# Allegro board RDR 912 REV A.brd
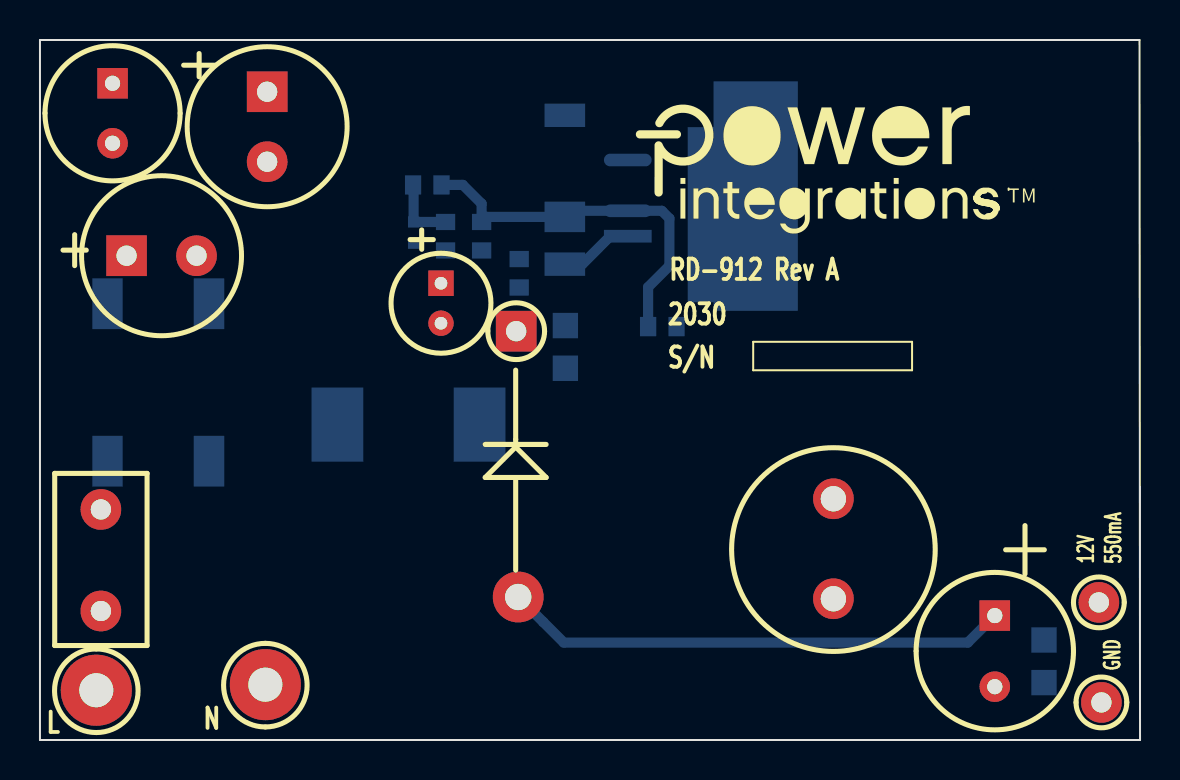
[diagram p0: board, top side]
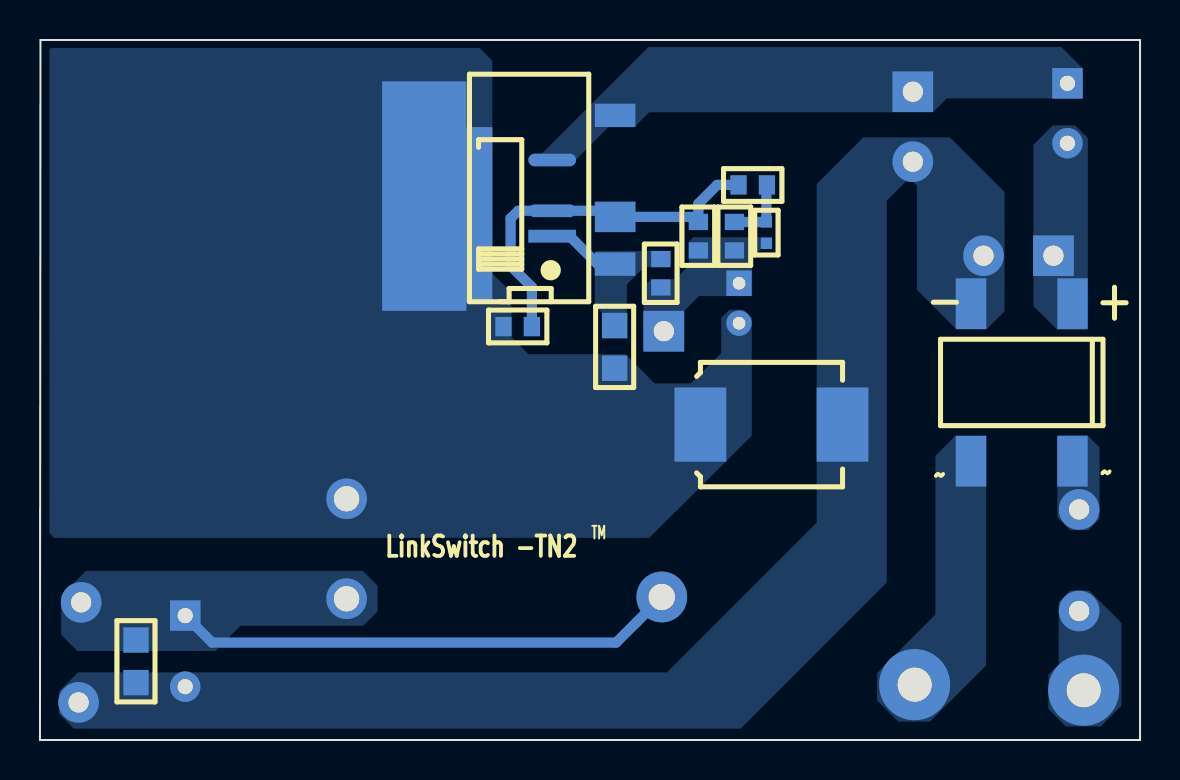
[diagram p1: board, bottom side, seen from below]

Outline 55.04 x 35.01 mm; copper layers: TOP, BOTTOM. Coordinates in mm from the lower left corner of the outline.
Outline path: 0,35.01 0,0 55.04,0 55.02,35.01 0,35.01

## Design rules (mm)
constraint set DEFAULT: min track width 0.508

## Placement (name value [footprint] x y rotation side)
C1  15  uF  [PI_POLCAPD8XH16XLLS3P5MM063H]  4.33 24.22 0 top
C2  15  uF  [PI_POLCAPD8XH16XLLS3P5MM063H]  11.37 32.42 270 top
C3  100 nF  [PISMC0805]  26.29 20.73 270 bottom
C4  10 uF  [PIPOLCAPCLYD5MMLS2MM025]  20.07 21.84 270 top
C5  220 uF  [PIPOLCAPCLYD320LS140030]  47.78 6.22 270 top
C6  1000 pF  [PISMC0603]  22.1 25.91 270 bottom
D1  DF06S-E3/45  [PISMDDFS]  3.38 21.77 180 bottom
D3  STTH3R06S  [PISMDO214AB12]  22 15.77 180 bottom
D4  1N4005GP-E3/54  [PIDV200X110X040DO41]  23.93 14.53 270 top
F1  1 A  [PI_RST_MICROFUSE]  3.05 11.53 270 top
L1  470 uH  [PI_CHOKE_RL5480-2_D2]  3.63 32.84 270 top
L2  680 uH  [PI_CHOKE_2P_D400LS200D05]  39.7 12.06 270 top
NOREF  -  []  55.02 35.01 270 top
NOREF#2  -  []  -150.78 61.85 0 top
NOREF#3  -  []  29.82 31.75 0 top
NOREF#4  -  []  -228.6 -137.16 0 top
NOREF#5  -  []  0 35.01 0 top
R1  2.49 k  [PISMR0603]  30.43 20.68 0 bottom
R2  12.1 k  [PISMR0603]  20.09 27.76 180 bottom
R3  27 k  [PISMR0603]  23.98 24.05 270 bottom
R4  20 k  [PISMR0805]  50.24 5 270 bottom
R5  6.81 k  [PISMR0603]  20.29 25.91 270 bottom
R6  0.0  [PISMR0402]  18.69 25.91 270 bottom
TP1  WHT  [PITPKEYSTONE125X125]  2.82 2.49 0 top
TP2  BLK  [PITPKEYSTONE125X125]  11.28 2.77 0 top
TP3  RED  [PITPKEYSTONE100X100]  52.98 6.88 270 top
TP4  BLK  [PITPKEYSTONE100X100]  53.11 1.88 270 top
U1  LNK3207D  [PISMSO8DNSHORT5678]  29.41 25.2 90 bottom
U2  LNK3207GN  [PIICSMD8CSHORT5678]  26.26 23.8 90 bottom

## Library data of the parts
C1 C2 = CAP POL: alternate symbols: (PI_POLCAPD8mmxlLS3p5mm063V)
C3 C6 = CAP NP
C4 = CAP POL
C5 = CAP POL: alternate symbols: (pipolcapclyd320ls140030430h)
D1 = DIODE BRIDGE_+-~~
D3 = DIODE
D4 = DIODE: alternate symbols: (pidv200x110x040do41A,pidax475x125040do41,pidv200x110x040do41wbead,pidax390x125040do41)
F1 = FUSE: alternate symbols: (pirstmicrofusehoz)
L1 = INDUCTOR_DOT2: alternate symbols: (pi_choke_RL5480-2H_d2)
L2 = INDUCTOR_DOT1: alternate symbols: (pi_choke_2p_d400ls200d05H)
R1-R5 = R
R6 = R: alternate symbols: (RC0402)
TP1-TP3 = TESTPOINT
TP4 = TESTPOINT: alternate symbols: (TP_TH_CR2_D1_1)
U1 U2 = LNK32XX_8C

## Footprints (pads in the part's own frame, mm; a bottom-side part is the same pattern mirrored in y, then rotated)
PI_CHOKE_2P_D400LS200D05
  round 2.032 hole 1.27: 1(0,0) 2(5,0)
PI_CHOKE_RL5480-2_D2
  rect 1.524x1.524 hole 0.762: 1(0,0)
  round 1.524 hole 0.762: 2(2.997,0)
PI_POLCAPD8XH16XLLS3P5MM063H
  rect 2.032x2.032 hole 1.016: 1(0,0)
  round 2.032 hole 1.016: 2(3.5,0)
PI_RST_MICROFUSE
  round 2.032 hole 1.016: 1(0,0) 2(5.08,0)
PIDV200X110X040DO41
  rect 2.032x2.032 hole 1.016: 1(-5.918,-0.102)
  round 2.54 hole 1.321: 2(7.376,0)
PIICSMD8CSHORT5678
  rect 1.168x2.032 smd: 1(0,0) 4(7.442,0) 5(7.442,8.636) 8(0,8.636)
  rect 1.524x2.032 smd: 2(2.362,0) 6(4.902,8.636) 7(2.362,8.636)
PIPOLCAPCLYD5MMLS2MM025
  rect 1.27x1.27 hole 0.635: 1(-1,0)
  round 1.27 hole 0.635: 2(1,0)
PIPOLCAPCLYD320LS140030
  rect 1.524x1.524 hole 0.762: 1(0,0)
  round 1.524 hole 0.762: 2(3.556,0)
PISMC0603
  rect 0.813x0.965 smd: 1(0,0) 2(1.422,0)
PISMC0805
  rect 1.27x1.27 smd: 1(0,0) 2(2.134,0)
PISMDDFS
  rect 1.524x2.54 smd: 1(0,0.051) 2(-5.08,0.051) 3(0,-7.823) 4(-5.08,-7.823)
PISMDO214AB12
  rect 2.591x3.708 smd: 1(0,0) 2(7.112,0)
PISMR0402
  rect 0.559x0.559 smd: 1(0,0) 2(1.067,0)
PISMR0603
  rect 0.813x0.965 smd: 1(0,0) 2(1.422,0)
PISMR0805
  rect 1.27x1.27 smd: 1(0,0) 2(2.134,0)
PISMSO8DNSHORT5678
  rect 0.635x2.388 smd: 1(0,0)
  oval 0.635x2.388 smd: 2(1.27,0) 4(3.81,0) 5(3.81,4.978) 6(2.54,4.978) 7(1.27,4.978) 8(0,4.978)
PITPKEYSTONE100X100
  round 2.032 hole 1.016: 1(0,0)
PITPKEYSTONE125X125
  round 3.556 hole 1.702: 1(0,0)

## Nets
SOURCE: U1.6 U1.7 U1.8 U2.6 U2.7 U2.8
N4183667: C2.1 L1.1 U1.4 U2.4
N4183681: C1.2 C2.2 C5.2 D1.2 D3.2 R4.2 TP4.1
N4183878: C3.2 C4.2 D3.1 L2.1 R1.2 U1.5(S) U2.5(S)
N4183892: C3.1 R3.1 U1.1 U2.1
N4184371: C6.1 R1.1 R2.1 U1.2 U2.2
N4185002: C5.1 D4.2 L2.2 R4.1 TP3.1
N4185015: C4.1 C6.2 D4.1 R3.2 R5.2 R6.2
N4189997: F1.2 TP1.1
N4190803: C1.1 D1.1 L1.2
N4191135: D1.3 F1.1
N4191491: D1.4 TP2.1
N4200643: R2.2 R5.1 R6.1

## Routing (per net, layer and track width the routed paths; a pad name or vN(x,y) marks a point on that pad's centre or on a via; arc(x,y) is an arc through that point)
N4183892: length 3.7
  BOTTOM w0.508: U1.1 28.54,25.2 27.14,23.8 U2.1
N4184371: length 18.9
  BOTTOM w0.508: R2.1 21.16,27.76 22.1,26.82 C6.1 22.35,26.16 U2.2 26.57,26.47 U1.2 31.11,26.47 31.5,26.09 31.5,23.72 30.43,22.65 R1.1
N4185002: length 25.4
  BOTTOM w0.508: C5.1 46.43,4.87 26.21,4.87 25.19,5.89 D4.2
N4200643: length 3.5
  BOTTOM w0.508: R2.2 18.69,27.74 R6.1 R5.1

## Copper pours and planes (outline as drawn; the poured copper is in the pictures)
SOURCE on BOTTOM (solid shape): 36.68,22.4 32.79,22.4 32.79,30.09 36.68,30.09
N4183667 on BOTTOM: 2.86,32.11 2.89,32.09 9.67,32.09 10.36,31.39 24.56,31.39 25.31,30.64 26.6,30.64 28.5,28.75 30.07,28.75 30.07,29.18 24.6,34.66 3.93,34.66 2.86,33.59
N4183681 on BOTTOM: 23.67,3.38 16.18,10.87 16.18,27.8 13.84,30.14 9.51,30.14 6.78,27.41 6.78,21.44 7.67,20.55 9.19,20.55 11.16,22.52 11.16,27.72 11.4,27.97 11.68,27.97 12.67,26.97 12.67,7.87 19.98,0.57 53.35,0.57 54.1,1.32 54.1,2.42 53.13,3.38
N4183878 on BOTTOM (solid shape): 37.26,21.89 32.41,21.89 32.41,30.65 37.26,30.65
N4183878 on BOTTOM (solid shape): 37.92,21.46 33.71,21.46 33.71,32.94 37.92,32.94
N4183878 on BOTTOM: 25.75,19.3 24.28,17.83 22.48,17.83 20.95,19.35 20.95,21.11 20.55,21.51 19.82,21.51 19.43,21.12 19.43,15.22 23.27,11.38 23.29,11.38 24.56,10.11 54.34,10.11 54.57,10.35 54.57,34.53 54.49,34.61 33.04,34.61 32.41,33.98 32.41,23.34 31.45,22.38 31.45,20.15 30.6,19.3
N4183892 on BOTTOM: 27.21,24.45 27.28,24.38 27.28,21.72 26.92,21.36 26.92,20.1 26.92,20.1 25.68,20.1 25.68,20.1 25.68,22.78 24.82,23.65 23.57,23.65 23.49,23.65 23.49,24.45
N4185002 on BOTTOM: 38.86,5.71 45.01,5.71 46.27,4.45 53.17,4.45 53.99,5.27 53.99,7.21 52.74,8.46 38.89,8.46 38.17,7.74 38.15,7.74 38.15,6.43
N4185015 on BOTTOM: 23.27,23.04 22.58,23.73 22.58,24.91 22.58,24.91 22.35,25.15 18.42,25.15 18.41,25.14 18.41,24.74 18.41,24.73 18.41,24.56 18.96,24.56 19.41,24.11 19.41,22.21 19.42,22.19 19.63,22.19 19.64,22.2 22.07,22.2 22.81,21.46 22.81,19.43 24.84,19.43 24.84,19.44 24.84,22.66 24.46,23.04
N4189997 on BOTTOM: 0.93,5.86 2.54,7.47 3.5,7.47 4.07,6.9 4.07,3.78 4.58,3.27 4.58,1.56 3.71,0.68 1.97,0.68 0.93,1.71
N4190803 on BOTTOM: 2.61,30.09 3.25,30.73 4.37,30.73 5.33,29.77 5.33,21.7 4.17,20.54 2.63,20.54 2.61,20.55 2.61,30.08
N4191135 on BOTTOM: 2.61,15.22 2.02,14.63 2.02,11.05 2.58,10.5 3.5,10.5 4.14,11.13 4.14,15.22
N4191491 on BOTTOM: 9.25,15.21 7.7,15.21 7.7,15.21 7.7,3.73 10.52,0.91 10.52,0.92 12.1,0.92 13.15,1.98 13.15,3.36 10.24,6.27 10.24,14.22

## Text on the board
Ref Des/Silkscreen Bottom: TM | LinkSwitch -TN2
Ref Des/Silkscreen Top: 12V | GND | 550mA | L | N | 2030 | S/N | RD-912 Rev A
User.6: 14.  FAB HOUSE LOGO,DATE CODE TO BE IN SILK SCREEN ONLY.DO NOT USE COPPER. | 13.  MATERIAL FR4 COPPER 2oz THICKNESS 0.062"
User.8: FIGURE | FINISHED_SIZE | 30.0 | 40.0 | 46.0 | 52.0 | 67.0 | DRILL CHART: TOP to BOTTOM | ALL UNITS ARE IN MILS | TOLERANCE_DRILL | +0.0/-0.0 | +3.0/-3.0 | PLATED | QTY | 4 | 2 | 7 | 1
